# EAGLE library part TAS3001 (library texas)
TAS3001C Digital Audio Processor
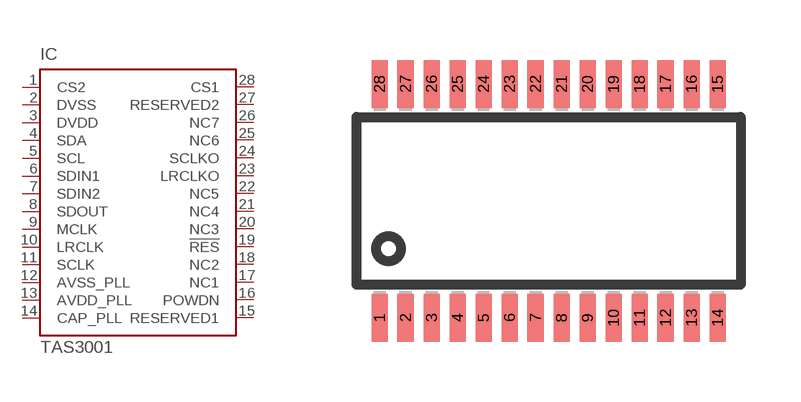
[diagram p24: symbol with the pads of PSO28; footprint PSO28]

Designator prefix IC

## TAS3001 (OC_FARNELL: unknown; OC_NEWARK: unknown)  [PSO28]
1  CS2  in
2  DVSS  pwr
3  DVDD  pwr
4  SDA
5  SCL
6  SDIN1  in
7  SDIN2  in
8  SDOUT  out
9  MCLK  in
10  LRCLK  in
11  SCLK  in
12  AVSS_PLL  pwr
13  AVDD_PLL  pwr
14  CAP_PLL  in
15  RESERVED1  in
16  POWDN  in
17  NC1  in
18  NC2  in
19  !RES  in
20  NC3  in
21  NC4  in
22  NC5  in
23  LRCLKO  out
24  SCLKO  out
25  NC6  in
26  NC7  in
27  RESERVED2  in
28  CS1  in

## Footprint PSO28 (pad centres in mm)
PLASTIC SMALL-OUTLINE PACKAGE PW (R-PDSO-G**) www.ti.com; tas3001.pdf
smd 0.4 x 1.2: 1 -4.225,-2.925; 2 -3.575,-2.925; 3 -2.925,-2.925; 4 -2.275,-2.925; 5 -1.625,-2.925; 6 -0.975,-2.925; 7 -0.325,-2.925; 8 0.325,-2.925; 9 0.975,-2.925; 10 1.625,-2.925; 11 2.275,-2.925; 12 2.925,-2.925; 13 3.575,-2.925; 14 4.225,-2.925; 15 4.225,2.925; 16 3.575,2.925; 17 2.925,2.925; 18 2.275,2.925; 19 1.625,2.925; 20 0.975,2.925; 21 0.325,2.925; 22 -0.325,2.925; 23 -0.975,2.925; 24 -1.625,2.925; 25 -2.275,2.925; 26 -2.925,2.925; 27 -3.575,2.925; 28 -4.225,2.925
